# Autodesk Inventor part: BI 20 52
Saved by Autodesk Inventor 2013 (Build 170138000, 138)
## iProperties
Created: 2012-12
Part Number: BI 20 52
Material: Générique
Document SubType Name: Modeling
Designer: jost thierry
Density: 1 g/cm^3
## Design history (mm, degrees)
node "BI 20 521"
node "BI 20 52"
node "Base1"
